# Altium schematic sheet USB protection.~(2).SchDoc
size A3; SheetNumber: 7; SheetTotal: 7
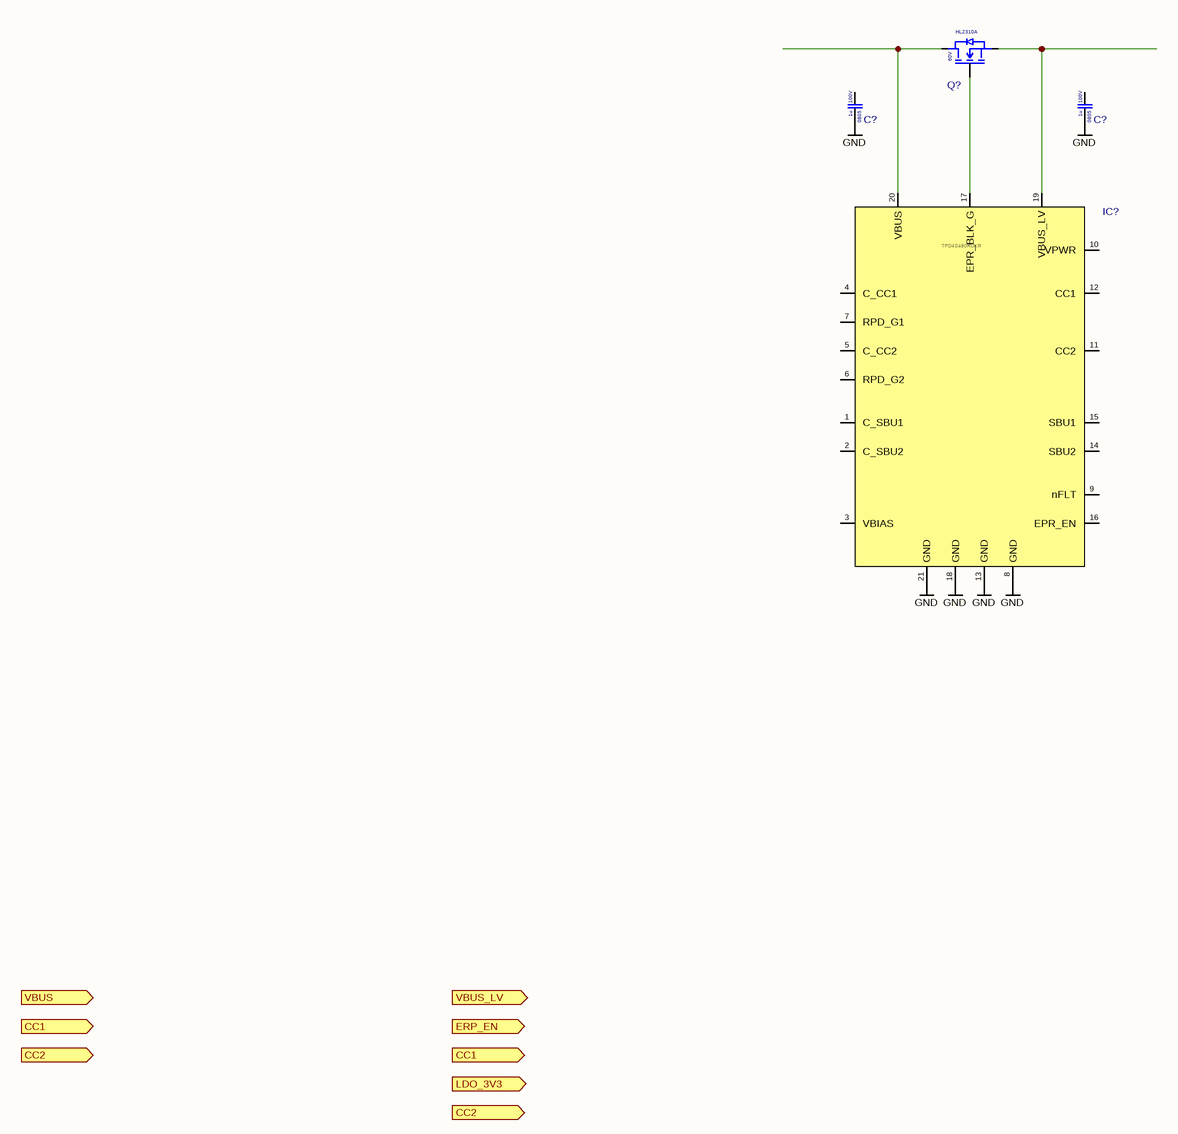
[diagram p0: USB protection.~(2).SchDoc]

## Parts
(Parts that share a designator on the sheet are numbered #1, #2 ... from top to bottom, then left to right.)
C?#1  Voltage Rating: 100V  Case Code (Imperial): 0805  Capacitance: 1u  [Cap_0805]  (hidden comment: CC0805KKX7R0BB105)
C?#2  Voltage Rating: 100V  Case Code (Imperial): 0805  Capacitance: 1u  [Cap_0805]  (hidden comment: CC0805KKX7R0BB105)
IC?  TPD4S480RUKR  [WQFN (20)]
Q?  Voltage: 60V  [SOT-23 GSD]  (hidden comment: HL2310A)

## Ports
CC1 (in, see Arhitecture[2B], USB PD[3C]), CC1 (out, see Arhitecture[2B], USB PD[3C]), CC2 (in, see Arhitecture[2B], USB PD[3C]), CC2 (out, see Arhitecture[2B], USB PD[3C]), ERP_EN (out, see Arhitecture[3B], USB PD[5B]), LDO_3V3 (in, see Arhitecture[3B], USB PD[3C]), VBUS (in, see Arhitecture[2B], Power path switch[3B]), VBUS_LV (out, see Arhitecture[3B], USB PD[3B])

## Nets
GND: C?#1.1 C?#2.1 IC?.8(GND) IC?.13(GND) IC?.18(GND) IC?.21(GND)
NetIC?_17: IC?.17(EPR_BLK_G) Q?.G
NetIC?_19: IC?.19(VBUS_LV) Q?.S
NetIC?_20: IC?.20(VBUS) Q?.D

Not connected (* = marked no-connect by the designer): C?#1 2; C?#2 2; IC? 1(C_SBU1) 2(C_SBU2) 3(VBIAS) 4(C_CC1) 5(C_CC2) 6(RPD_G2) 7(RPD_G1) 9(nFLT) 10(VPWR) 11(CC2) 12(CC1) 14(SBU2) 15(SBU1) 16(EPR_EN)

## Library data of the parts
C?#1 C?#2 = CC0805KKX7R0BB105: Cap 1uF 100V 0805 X7R; Manufacturer: Yageo
IC? = TPD4S480RUKR: USB PD protection IC; Manufacturer: Texas Instruments
Q? = HL2310A: nMOS 60V 3A SOT-23; Manufacturer: hongjiacheng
